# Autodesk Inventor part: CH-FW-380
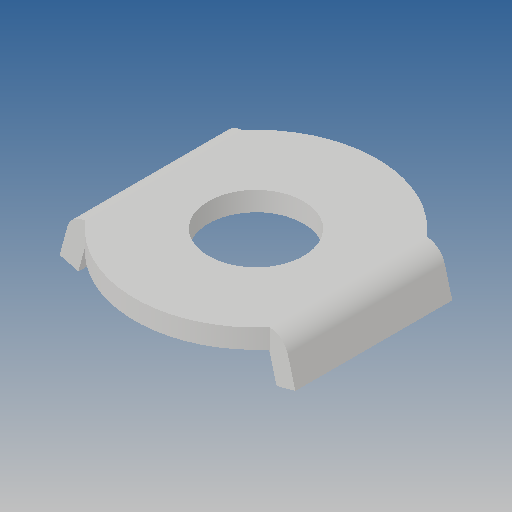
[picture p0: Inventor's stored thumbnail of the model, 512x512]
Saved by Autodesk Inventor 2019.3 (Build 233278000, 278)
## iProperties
Created: 2012-09
Part Number: CH-FW-380
Material: Ogólny
Document SubType Name: Modeling
Designer: CADENGINEERING4
Density: 1 g/cm^3
Appearance: Domyślna
Author: CADENGINEERING4
Revision Number: ÈÎºÎ
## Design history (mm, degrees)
feature "ÇÐ³ý-À­Éì1"
node "Bryła1"
